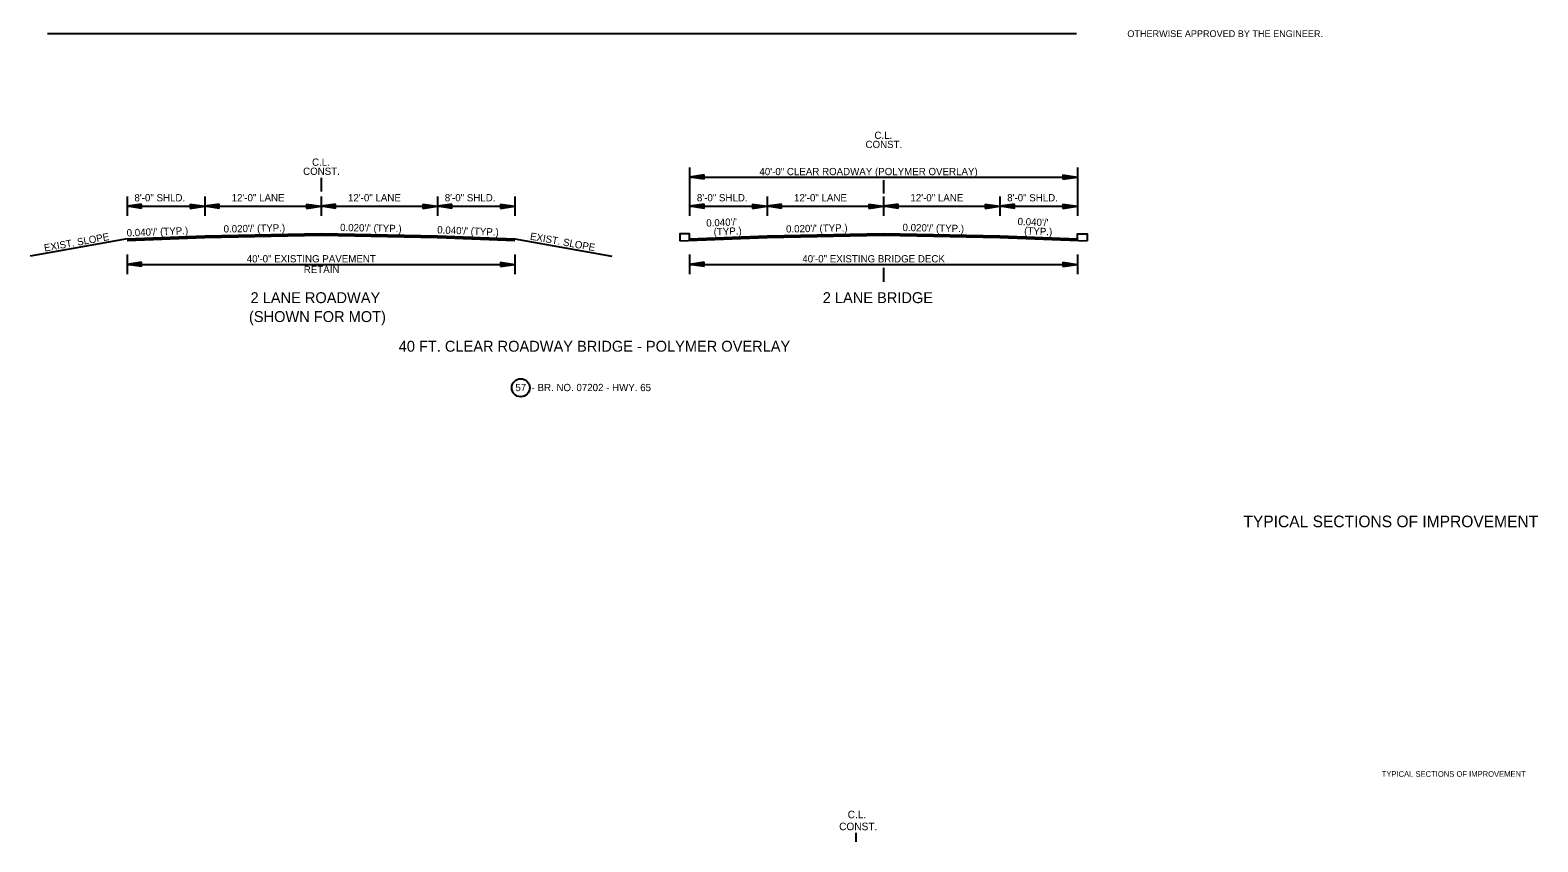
# Model space of a CAD drawing. Extents: x 550980 to 1930787, y -1972975 to 596640.
# Drawn here: x 550991 to 552546, y -1972051 to -1971213 of the extents above; entities that cross this region are included whole.
import ezdxf

# ---------------------------------------------------------------- set-up
doc = ezdxf.new("R2010")
doc.units = 0
for name, color, linetype in [('R_Border', 7, 'Continuous'), ('R_Border Notes', 7, 'Continuous'), ('R_Draft', 7, 'Continuous'), ('S_AREA_CALC', 7, 'Continuous')]:
    doc.layers.add(name, color=color, linetype=linetype)

# ---------------------------------------------------------------- blocks, each defined once
blk = doc.blocks.new('ARROW')
at = {"layer": 'R_Draft'}
for p, q in [((-2, 0.3), (0, 0)), ((-2, 0.3), (-2, -0.3)), ((-2, 0.25), (-0.334, 0)), ((-2, 0.199), (-0.678, 0)), ((-2, 0.149), (-1.011, 0)), ((-2, 0.097), (-1.35, 0)), ((-2, 0.047), (-1.684, 0)), ((-2, -0.3), (0, 0)), ((-2, -0.098), (-1.35, 0)), ((-2, -0.199), (-0.678, 0)), ((-2, -0.25), (-0.334, 0)), ((-2, -0.149), (-1.011, 0)), ((-2, -0.047), (-1.684, 0))]:
    blk.add_line(p, q, dxfattribs=at)
blk = doc.blocks.new('BPPOLY')
at = {"layer": 'R_Border'}
blk.add_circle((0, 0), 9.34, dxfattribs=at)

msp = doc.modelspace()

# ---------------------------------------------------------------- linework, layer by layer
at = {"layer": 'R_Border'}
for p, q in [((551009, -1971216.9), (552070.2, -1971216.9)), ((551671.1, -1971355), (551671.1, -1971405)), ((552071.1, -1971355), (552071.1, -1971405)), ((551291.1, -1971365.7), (551291.1, -1971380)), ((551671.1, -1971365), (552071.1, -1971365)), ((551871.1, -1971368), (551871.1, -1971382)), ((551091.1, -1971385), (551091.1, -1971405)), ((551171.1, -1971385), (551171.1, -1971405)), ((551291.1, -1971385), (551291.1, -1971405)), ((551411.1, -1971385), (551411.1, -1971405)), ((551491.1, -1971385), (551491.1, -1971405)), ((551751.1, -1971385), (551751.1, -1971405)), ((551871.1, -1971385), (551871.1, -1971405)), ((551991.1, -1971385), (551991.1, -1971405)), ((551091.1, -1971395), (551491.1, -1971395)), ((551671.1, -1971395), (552071.1, -1971395)), ((551091.1, -1971428.6), (550991.1, -1971446.6)), ((551491.1, -1971428.6), (551591.1, -1971446.6)), ((551091.1, -1971445), (551091.1, -1971465)), ((551491.1, -1971445), (551491.1, -1971465)), ((551671.1, -1971445), (551671.1, -1971465)), ((552071.1, -1971445), (552071.1, -1971465)), ((551091.1, -1971455), (551491.1, -1971455)), ((551671.1, -1971455), (552071.1, -1971455)), ((551871.1, -1971458.7), (551871.1, -1971473.2))]:
    msp.add_line(p, q, dxfattribs=at)
for points in [[(551091.1, -1971428.6), (551171.1, -1971425.4), (551291.1, -1971423), (551411.1, -1971425.4), (551491.1, -1971428.6)], [(551091.1, -1971428.9), (551171.1, -1971425.7), (551291.1, -1971423.3), (551411.1, -1971425.7), (551491.1, -1971428.9)], [(551091.1, -1971429.2), (551171.1, -1971426), (551291.1, -1971423.6), (551411.1, -1971426), (551491.1, -1971429.2)], [(551091.1, -1971429.5), (551171.1, -1971426.3), (551291.1, -1971423.9), (551411.1, -1971426.3), (551491.1, -1971429.5)], [(551091.1, -1971429.8), (551171.1, -1971426.6), (551291.1, -1971424.2), (551411.1, -1971426.6), (551491.1, -1971429.8)], [(551091.1, -1971430.1), (551171.1, -1971426.9), (551291.1, -1971424.5), (551411.1, -1971426.9), (551491.1, -1971430.1)], [(551091.1, -1971430.4), (551171.1, -1971427.2), (551291.1, -1971424.8), (551411.1, -1971427.2), (551491.1, -1971430.4)], [(551671.1, -1971430.1), (551671.1, -1971423.6), (551661.1, -1971423.6), (551661.1, -1971430.8)], [(551661.1, -1971430.8), (551751.1, -1971427.2), (551871.1, -1971424.8), (551991.1, -1971427.2), (552081.1, -1971430.8)], [(551671.1, -1971428.6), (551751.1, -1971425.4), (551871.1, -1971423), (551991.1, -1971425.4), (552071.1, -1971428.6)], [(551671.1, -1971428.9), (551751.1, -1971425.7), (551871.1, -1971423.3), (551991.1, -1971425.7), (552071.1, -1971428.9)], [(551671.1, -1971429.2), (551751.1, -1971426), (551871.1, -1971423.6), (551991.1, -1971426), (552071.1, -1971429.2)], [(551671.1, -1971429.5), (551751.1, -1971426.3), (551871.1, -1971423.9), (551991.1, -1971426.3), (552071.1, -1971429.5)], [(551671.1, -1971429.8), (551751.1, -1971426.6), (551871.1, -1971424.2), (551991.1, -1971426.6), (552071.1, -1971429.8)], [(551671.1, -1971430.1), (551751.1, -1971426.9), (551871.1, -1971424.5), (551991.1, -1971426.9), (552071.1, -1971430.1)], [(552071.1, -1971430.8), (552071.1, -1971423.6), (552081.1, -1971423.6), (552081.1, -1971430.8)]]:
    msp.add_lwpolyline(points, dxfattribs=at)
at = {"layer": 'R_Draft'}
msp.add_line((551843.1, -1972050.8), (551843.1, -1972041.5), dxfattribs=at)

# ---------------------------------------------------------------- block references
at = {"layer": 'R_Border', "xscale": 7.5, "yscale": 7.5, "rotation": 180}
for p in [(551671.1, -1971365), (551091.1, -1971395), (551171.1, -1971395), (551291.1, -1971395), (551411.1, -1971395), (551671.1, -1971395), (551751.1, -1971395), (551871.1, -1971395), (551991.1, -1971395), (551091.1, -1971455), (551671.1, -1971455)]:
    msp.add_blockref('ARROW', p, dxfattribs=at)
at = {"layer": 'R_Border', "xscale": 7.5, "yscale": 7.5}
for p in [(552071.1, -1971365), (551171.1, -1971395), (551291.1, -1971395), (551411.1, -1971395), (551491.1, -1971395), (551751.1, -1971395), (551871.1, -1971395), (551991.1, -1971395), (552071.1, -1971395), (551491.1, -1971455), (552071.1, -1971455)]:
    msp.add_blockref('ARROW', p, dxfattribs=at)
at = {"layer": 'R_Border'}
msp.add_blockref('BPPOLY', (551497.1, -1971582.3), dxfattribs=at)

# ---------------------------------------------------------------- texts
for s, height, p in [('CONST.', 7.5, (551852.6, -1971335)), ('C.L.', 7.5, (551861.8, -1971325.6)), ('CONST.', 7.5, (551272.6, -1971362.7)), ('C.L.', 7.5, (551281.8, -1971353.3)), ('40\'-0" CLEAR ROADWAY (POLYMER OVERLAY)', 7.5, (551743.2, -1971363)), ('8\'-0" SHLD.', 7.5, (551098.7, -1971390)), ('12\'-0" LANE', 7.5, (551198.9, -1971390)), ('12\'-0" LANE', 7.5, (551318.9, -1971390)), ('8\'-0" SHLD.', 7.5, (551418.7, -1971390)), ('8\'-0" SHLD.', 7.5, (551678.7, -1971390)), ('12\'-0" LANE', 7.5, (551778.9, -1971390)), ('12\'-0" LANE', 7.5, (551898.9, -1971390)), ('8\'-0" SHLD.', 7.5, (551998.7, -1971390)), ('40\'-0" EXISTING PAVEMENT', 7.5, (551214.5, -1971453)), ('40\'-0" EXISTING BRIDGE DECK', 7.5, (551787.4, -1971453)), ('RETAIN', 7.5, (551273.3, -1971464)), ('2 LANE ROADWAY', 11.25, (551218.4, -1971495)), ('2 LANE BRIDGE', 11.25, (551808.5, -1971495)), ('(SHOWN FOR MOT)', 11.25, (551216.8, -1971514.5)), ('40 FT. CLEAR ROADWAY BRIDGE - POLYMER OVERLAY', 11.25, (551371.2, -1971545.1))]:
    msp.add_text(s, height=height, dxfattribs=at).set_placement(p)
for s, height, rotation, p in [("0.040'/' (TYP.)", 7.5, 2.2916, (551090.8, -1971426.3)), ("0.020'/' (TYP.)", 7.5, 1.1458, (551190.7, -1971422.2)), ("0.020'/' (TYP.)", 7.5, 358.8542, (551310.7, -1971420.6)), ("0.040'/' (TYP.)", 7.5, 357.7084, (551410.8, -1971423)), ("0.040'/'", 7.5, 2.2916, (551688.5, -1971416.1)), ('(TYP.)', 7.5, 2.2916, (551696.1, -1971425.2)), ("0.020'/' (TYP.)", 7.5, 1.1458, (551770.7, -1971422.2)), ("0.020'/' (TYP.)", 7.5, 358.8542, (551890.7, -1971420.6)), ("0.040'/'", 7.5, 357.7084, (552009.3, -1971414.4)), ('(TYP.)', 7.5, 357.7084, (552016.1, -1971424)), ('EXIST. SLOPE', 7.5, 10.204, (551006.2, -1971441.9)), ('EXIST. SLOPE', 7.5, 349.796, (551506.2, -1971429.4)), ('TYPICAL SECTIONS OF IMPROVEMENT', 12, 360, (552242.3, -1971726.2))]:
    msp.add_text(s, height=height, rotation=rotation, dxfattribs=at).set_placement(p)
at = {"layer": 'R_Border Notes'}
msp.add_text('OTHERWISE APPROVED BY THE ENGINEER.', height=7, dxfattribs=at).set_placement((552122.6, -1971220.5))
at = {"layer": 'R_Draft'}
for s, height, p in [('57  - BR. NO. 07202 - HWY. 65', 7.5, (551491.5, -1971585.8)), ('C.L.', 7.8, (551834.2, -1972026.5)), ('CONST.', 7.8, (551825.4, -1972038.8))]:
    msp.add_text(s, height=height, dxfattribs=at).set_placement(p)
at = {"layer": 'S_AREA_CALC'}
msp.add_text('TYPICAL SECTIONS OF IMPROVEMENT', height=5.862, rotation=360, dxfattribs=at).set_placement((552384.9, -1971983.7))

doc.saveas('drawing.dxf')
